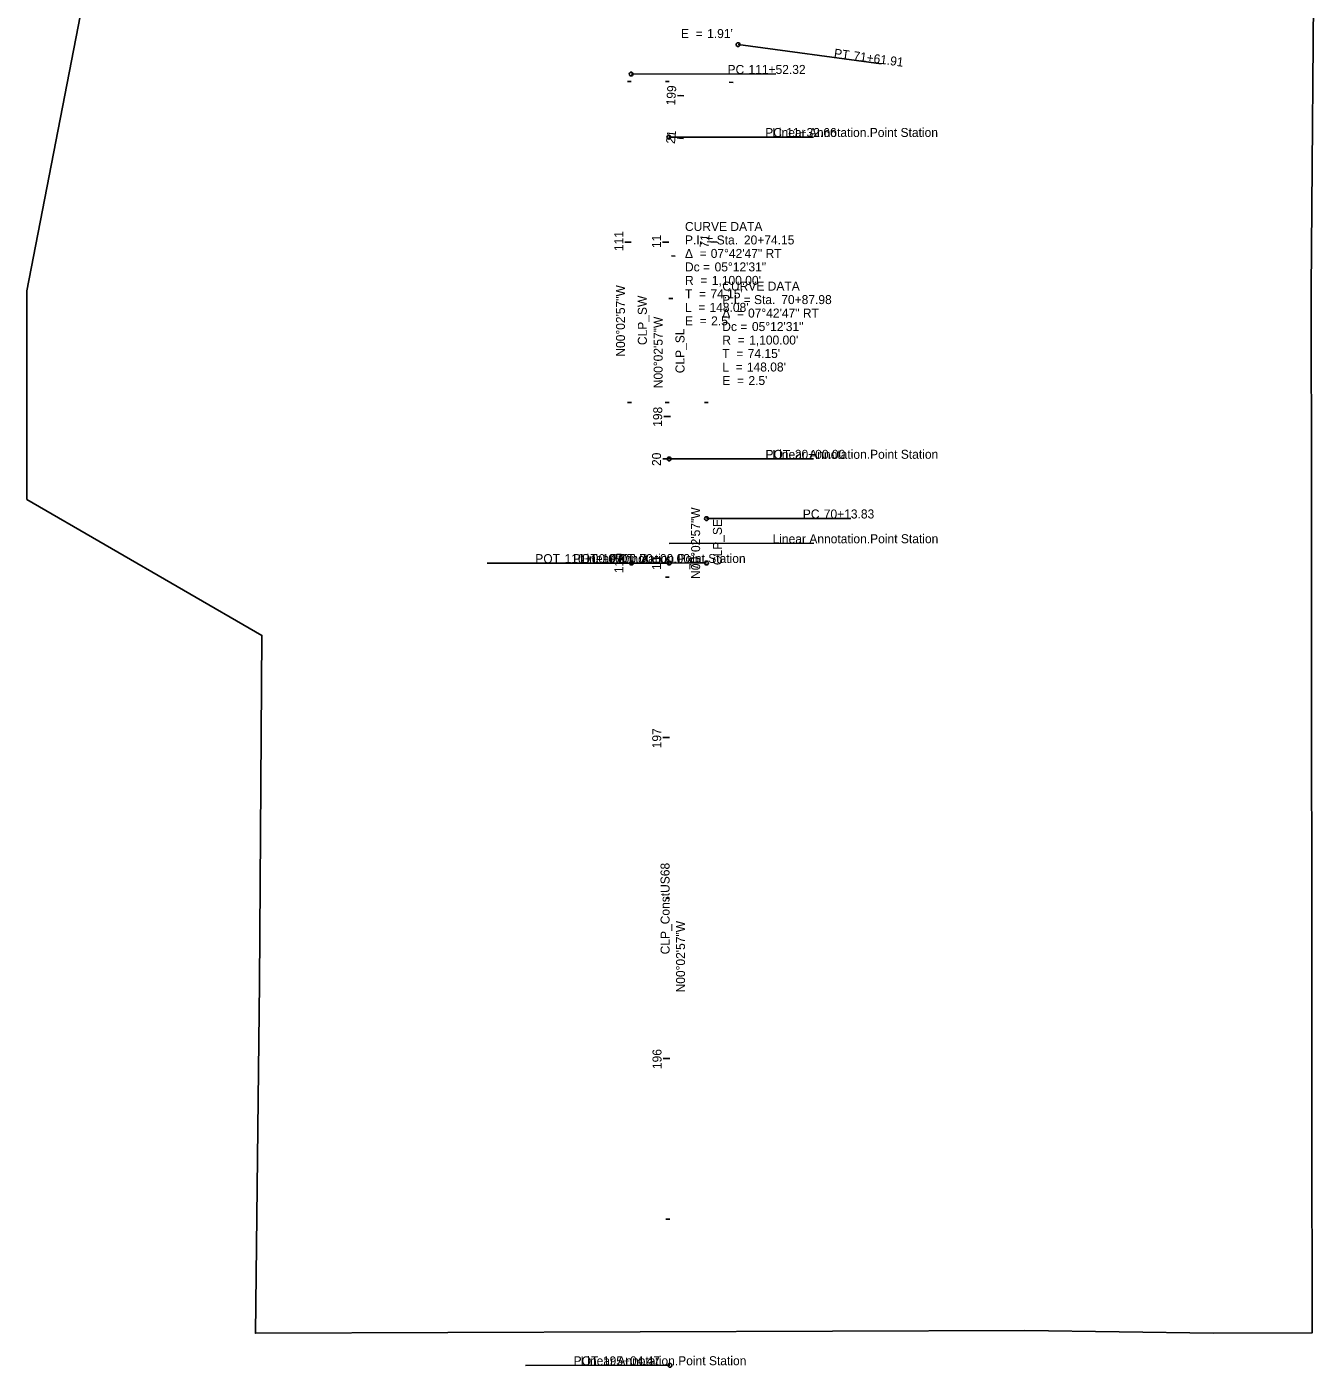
# Model space of a CAD drawing. Extents: x 1564517 to 1565226, y 635740 to 637455.
# Drawn here: x 1564587.2 to 1564988.1, y 635740 to 636157.6 of the extents above; entities that cross this region are included whole.
import ezdxf

# ---------------------------------------------------------------- set-up
doc = ezdxf.new("R2010")
doc.units = 0
for name, color, linetype in [('GE_P_Alignment_1000_Bearings', 7, 'Continuous'), ('GE_P_Alignment_1000_Distances', 7, 'Continuous'), ('GE_P_Alignment_100_Cardinal_Points', 7, 'Continuous'), ('GE_P_Alignment_500_Bearings', 7, 'Continuous'), ('GE_P_Alignment_500_Cardinal_Points', 7, 'Continuous'), ('GE_P_Alignment_500_Distances', 7, 'Continuous'), ('GK_Drainage_Nodes', 7, 'Continuous'), ('SC_Scratch10', 7, 'Continuous'), ('TX_P_1000', 7, 'Continuous'), ('UT_P_Water', 7, 'Continuous'), ('UT_P_Water_Cells', 7, 'Continuous'), ('UT_X_Electric', 7, 'Continuous'), ('UT_X_Sanitary_Pressure_Line', 7, 'Continuous'), ('UT_X_Water_Cells', 7, 'Continuous')]:
    doc.layers.add(name, color=color, linetype=linetype)

msp = doc.modelspace()

# ---------------------------------------------------------------- linework, layer by layer
at = {"layer": 'GE_P_Alignment_100_Cardinal_Points'}
msp.add_circle((1564787.45, 635740.63), 0.6, dxfattribs=at)
at = {"layer": 'GE_P_Alignment_500_Cardinal_Points'}
msp.add_line((1564787.45, 635740.63), (1564742.45, 635740.59), dxfattribs=at)
msp.add_circle((1564787.45, 635740.63), 0.6, dxfattribs=at)
at = {"layer": 'TX_P_1000'}
for p, q in [((1564787.13, 636123.19), (1564832.13, 636123.23)), ((1564787.21, 636022.95), (1564832.21, 636022.99)), ((1564787.24, 635996.63), (1564832.24, 635996.67)), ((1564787.24, 635990.53), (1564742.24, 635990.49)), ((1564787.45, 635740.63), (1564742.45, 635740.59))]:
    msp.add_line(p, q, dxfattribs=at)
at = {"layer": 'UT_P_Water_Cells'}
for p, q in [((1564808.66, 636152.01), (1564853.26, 636146.01)), ((1564775.39, 636142.84), (1564820.39, 636142.88)), ((1564791.8, 636136.06), (1564790.61, 636136.14)), ((1564787.13, 636123.19), (1564832.13, 636123.23)), ((1564791.67, 636122.81), (1564790.47, 636122.92)), ((1564775.43, 636090.52), (1564774.23, 636090.52)), ((1564787.15, 636090.53), (1564785.95, 636090.53)), ((1564802.14, 636090.45), (1564800.94, 636090.55)), ((1564787.58, 636036.16), (1564786.38, 636036.18)), ((1564787.21, 636022.95), (1564785.21, 636022.94)), ((1564787.21, 636022.95), (1564832.21, 636022.99)), ((1564798.84, 636004.37), (1564843.84, 636004.41)), ((1564775.52, 635990.52), (1564730.52, 635990.48)), ((1564787.24, 635990.53), (1564742.24, 635990.49)), ((1564798.85, 635990.54), (1564753.85, 635990.5)), ((1564775.52, 635990.52), (1564773.52, 635990.52)), ((1564787.24, 635990.53), (1564785.24, 635990.53)), ((1564798.85, 635990.54), (1564796.85, 635990.54)), ((1564787.29, 635936.16), (1564786.09, 635936.16)), ((1564787.37, 635836.16), (1564786.17, 635836.16))]:
    msp.add_line(p, q, dxfattribs=at)
for centre in [(1564808.66, 636152.01), (1564775.39, 636142.84), (1564787.13, 636123.19), (1564787.21, 636022.95), (1564798.84, 636004.37), (1564775.52, 635990.52), (1564787.24, 635990.53), (1564798.85, 635990.54)]:
    msp.add_circle(centre, 0.6, dxfattribs=at)
at = {"layer": 'UT_X_Electric'}
msp.add_lwpolyline([(1564658.34, 635750.59), (1564898, 635751.43), (1564898, 635751.43), (1564898, 635751.43), (1564956.75, 635750.68), (1564987.45, 635750.7), (1564987.39, 635815.7), (1564987.33, 635880.7), (1564987.28, 635945.7), (1564987.22, 636010.7), (1564987.17, 636075.7), (1564988.09, 636191.25), (1564617.12, 636229.41), (1564587.17, 636075.36), (1564587.22, 636010.36), (1564660.39, 635967.97), (1564659.6, 635859.64), (1564658.34, 635750.59), (1564658.34, 635750.59)], close=True, dxfattribs=at)
at = {"layer": 'UT_X_Sanitary_Pressure_Line'}
for p, q in [((1564808.66, 636152.01), (1564853.26, 636146.01)), ((1564775.39, 636142.84), (1564820.39, 636142.88)), ((1564787.13, 636123.19), (1564832.13, 636123.23)), ((1564787.21, 636022.95), (1564785.21, 636022.94)), ((1564787.21, 636022.95), (1564832.21, 636022.99)), ((1564798.84, 636004.37), (1564843.84, 636004.41)), ((1564775.52, 635990.52), (1564730.52, 635990.48)), ((1564787.24, 635990.53), (1564742.24, 635990.49)), ((1564798.85, 635990.54), (1564753.85, 635990.5)), ((1564775.52, 635990.52), (1564773.52, 635990.52)), ((1564787.24, 635990.53), (1564785.24, 635990.53)), ((1564798.85, 635990.54), (1564796.85, 635990.54))]:
    msp.add_line(p, q, dxfattribs=at)
for centre in [(1564808.66, 636152.01), (1564775.39, 636142.84), (1564787.13, 636123.19), (1564787.21, 636022.95), (1564798.84, 636004.37), (1564775.52, 635990.52), (1564787.24, 635990.53), (1564798.85, 635990.54)]:
    msp.add_circle(centre, 0.6, dxfattribs=at)
at = {"layer": 'UT_X_Water_Cells'}
for p, q in [((1564775.39, 636140.52), (1564774.19, 636140.52)), ((1564787.25, 636140.53), (1564786.06, 636140.55)), ((1564807.14, 636140.2), (1564805.95, 636140.35)), ((1564791.8, 636136.06), (1564789.81, 636136.19)), ((1564791.67, 636122.81), (1564789.68, 636122.99)), ((1564775.43, 636090.52), (1564773.43, 636090.52)), ((1564787.15, 636090.53), (1564785.15, 636090.53)), ((1564802.14, 636090.45), (1564800.14, 636090.61)), ((1564789.09, 636086.14), (1564787.89, 636086.19)), ((1564788.31, 636072.93), (1564787.11, 636072.98)), ((1564775.47, 636040.52), (1564774.27, 636040.52)), ((1564787.2, 636040.53), (1564786, 636040.53)), ((1564799.4, 636040.53), (1564798.2, 636040.57)), ((1564787.58, 636036.16), (1564785.58, 636036.2)), ((1564787.21, 636022.95), (1564785.21, 636022.94)), ((1564775.52, 635990.52), (1564773.52, 635990.52)), ((1564787.24, 635990.53), (1564785.24, 635990.53)), ((1564798.85, 635990.54), (1564796.85, 635990.54)), ((1564787.24, 635986.16), (1564786.04, 635986.16)), ((1564787.29, 635936.16), (1564785.29, 635936.16)), ((1564787.33, 635886.16), (1564786.13, 635886.16)), ((1564787.37, 635836.16), (1564785.37, 635836.16)), ((1564787.42, 635786.16), (1564786.22, 635786.16))]:
    msp.add_line(p, q, dxfattribs=at)
msp.add_circle((1564787.13, 636123.19), 0.6, dxfattribs=at)

# ---------------------------------------------------------------- texts
at = {"layer": 'GE_P_Alignment_1000_Bearings'}
msp.add_text('N00°02\'57"W', height=2.8, rotation=90.0491, dxfattribs=at).set_placement((1564792.16, 635856.77))
at = {"layer": 'GE_P_Alignment_1000_Distances'}
msp.add_text('CLP_ConstUS68', height=2.8, rotation=90.0491, dxfattribs=at).set_placement((1564787.35, 635868.63))
at = {"layer": 'GE_P_Alignment_500_Bearings'}
msp.add_text('N00°02\'57"W', height=2.8, rotation=90.0491, dxfattribs=at).set_placement((1564792.16, 635856.77))
at = {"layer": 'GE_P_Alignment_500_Cardinal_Points'}
for s, p in [('POT', (1564757.45, 635740.61)), ('195+04.47', (1564766.58, 635740.61))]:
    msp.add_text(s, height=2.8, rotation=0.0491, dxfattribs=at).set_placement(p)
at = {"layer": 'GE_P_Alignment_500_Distances'}
msp.add_text('CLP_ConstUS68', height=2.8, rotation=90.0491, dxfattribs=at).set_placement((1564787.35, 635868.63))
at = {"layer": 'GK_Drainage_Nodes'}
for s, p in [('E  = ', (1564790.87, 636154.06)), ("1.91'", (1564799.03, 636154.06)), ('CURVE DATA', (1564792.13, 636093.97)), ('P.I. = Sta. ', (1564792.13, 636089.77)), ('20+74.15', (1564810.49, 636089.77)), ('Δ  = ', (1564792.13, 636085.57)), ('07°42\'47" RT', (1564800.15, 636085.57)), ('Dc = ', (1564792.13, 636081.37)), ('05°12\'31"', (1564801.36, 636081.37)), ('R  = ', (1564792.13, 636077.17)), ("1,100.00'", (1564800.49, 636077.17)), ('CURVE DATA', (1564803.75, 636075.39)), ('T  = ', (1564792.13, 636072.97)), ("74.15'", (1564800.06, 636072.97)), ('P.I. = Sta. ', (1564803.75, 636071.19)), ('70+87.98', (1564822.12, 636071.19)), ('L  = ', (1564792.13, 636068.77)), ("148.08'", (1564799.77, 636068.77)), ('Δ  = ', (1564803.75, 636066.99)), ('07°42\'47" RT', (1564811.77, 636066.99)), ('E  = ', (1564792.13, 636064.57)), ("2.5'", (1564800.28, 636064.57)), ('Dc = ', (1564803.75, 636062.79)), ('05°12\'31"', (1564812.99, 636062.79)), ('R  = ', (1564803.75, 636058.59)), ("1,100.00'", (1564812.12, 636058.59)), ('T  = ', (1564803.75, 636054.39)), ("74.15'", (1564811.68, 636054.39)), ('L  = ', (1564803.75, 636050.19)), ("148.08'", (1564811.4, 636050.19)), ('E  = ', (1564803.75, 636045.99)), ("2.5'", (1564811.9, 636045.99))]:
    msp.add_text(s, height=2.8, dxfattribs=at).set_placement(p)
for s, p in [('N00°02\'57"W', (1564773.46, 636054.81)), ('CLP_SW', (1564780.26, 636058.41)), ('N00°02\'57"W', (1564785.19, 636044.99)), ('CLP_SL', (1564791.99, 636049.64)), ('N00°02\'57"W', (1564796.86, 635985.59)), ('CLP_SE', (1564803.65, 635989.87))]:
    msp.add_text(s, height=2.8, rotation=90.0491, dxfattribs=at).set_placement(p)
at = {"layer": 'SC_Scratch10'}
for s, p in [('E  = ', (1564790.87, 636154.06)), ("1.91'", (1564799.03, 636154.06)), ('CURVE DATA', (1564792.13, 636093.97)), ('P.I. = Sta. ', (1564792.13, 636089.77)), ('20+74.15', (1564810.49, 636089.77)), ('Δ  = ', (1564792.13, 636085.57)), ('07°42\'47" RT', (1564800.15, 636085.57)), ('Dc = ', (1564792.13, 636081.37)), ('05°12\'31"', (1564801.36, 636081.37)), ('R  = ', (1564792.13, 636077.17)), ("1,100.00'", (1564800.49, 636077.17)), ('CURVE DATA', (1564803.75, 636075.39)), ('T  = ', (1564792.13, 636072.97)), ("74.15'", (1564800.06, 636072.97)), ('P.I. = Sta. ', (1564803.75, 636071.19)), ('70+87.98', (1564822.12, 636071.19)), ('L  = ', (1564792.13, 636068.77)), ("148.08'", (1564799.77, 636068.77)), ('Δ  = ', (1564803.75, 636066.99)), ('07°42\'47" RT', (1564811.77, 636066.99)), ('E  = ', (1564792.13, 636064.57)), ("2.5'", (1564800.28, 636064.57)), ('Dc = ', (1564803.75, 636062.79)), ('05°12\'31"', (1564812.99, 636062.79)), ('R  = ', (1564803.75, 636058.59)), ("1,100.00'", (1564812.12, 636058.59)), ('T  = ', (1564803.75, 636054.39)), ("74.15'", (1564811.68, 636054.39)), ('L  = ', (1564803.75, 636050.19)), ("148.08'", (1564811.4, 636050.19)), ('E  = ', (1564803.75, 636045.99)), ("2.5'", (1564811.9, 636045.99))]:
    msp.add_text(s, height=2.8, dxfattribs=at).set_placement(p)
for s, p in [('N00°02\'57"W', (1564773.46, 636054.81)), ('CLP_SW', (1564780.26, 636058.41)), ('N00°02\'57"W', (1564785.19, 636044.99)), ('CLP_SL', (1564791.99, 636049.64)), ('N00°02\'57"W', (1564796.86, 635985.59)), ('CLP_SE', (1564803.65, 635989.87))]:
    msp.add_text(s, height=2.8, rotation=90.0491, dxfattribs=at).set_placement(p)
at = {"layer": 'TX_P_1000'}
for p in [(1564819.3, 636123.22), (1564819.39, 636022.97), (1564819.41, 635996.66), (1564759.41, 635990.51), (1564759.63, 635740.61)]:
    msp.add_text('Linear Annotation.Point Station', height=2.8, rotation=0.0491, dxfattribs=at).set_placement(p)
at = {"layer": 'UT_P_Water'}
for s, p in [('E  = ', (1564790.87, 636154.06)), ("1.91'", (1564799.03, 636154.06)), ('CURVE DATA', (1564792.13, 636093.97)), ('P.I. = Sta. ', (1564792.13, 636089.77)), ('20+74.15', (1564810.49, 636089.77)), ('Δ  = ', (1564792.13, 636085.57)), ('07°42\'47" RT', (1564800.15, 636085.57)), ('Dc = ', (1564792.13, 636081.37)), ('05°12\'31"', (1564801.36, 636081.37)), ('R  = ', (1564792.13, 636077.17)), ("1,100.00'", (1564800.49, 636077.17)), ('CURVE DATA', (1564803.75, 636075.39)), ('T  = ', (1564792.13, 636072.97)), ("74.15'", (1564800.06, 636072.97)), ('P.I. = Sta. ', (1564803.75, 636071.19)), ('70+87.98', (1564822.12, 636071.19)), ('L  = ', (1564792.13, 636068.77)), ("148.08'", (1564799.77, 636068.77)), ('Δ  = ', (1564803.75, 636066.99)), ('07°42\'47" RT', (1564811.77, 636066.99)), ('E  = ', (1564792.13, 636064.57)), ("2.5'", (1564800.28, 636064.57)), ('Dc = ', (1564803.75, 636062.79)), ('05°12\'31"', (1564812.99, 636062.79)), ('R  = ', (1564803.75, 636058.59)), ("1,100.00'", (1564812.12, 636058.59)), ('T  = ', (1564803.75, 636054.39)), ("74.15'", (1564811.68, 636054.39)), ('L  = ', (1564803.75, 636050.19)), ("148.08'", (1564811.4, 636050.19)), ('E  = ', (1564803.75, 636045.99)), ("2.5'", (1564811.9, 636045.99))]:
    msp.add_text(s, height=2.8, dxfattribs=at).set_placement(p)
for s, p in [('N00°02\'57"W', (1564773.46, 636054.81)), ('CLP_SW', (1564780.26, 636058.41)), ('N00°02\'57"W', (1564785.19, 636044.99)), ('CLP_SL', (1564791.99, 636049.64)), ('N00°02\'57"W', (1564796.86, 635985.59)), ('CLP_SE', (1564803.65, 635989.87))]:
    msp.add_text(s, height=2.8, rotation=90.0491, dxfattribs=at).set_placement(p)
at = {"layer": 'UT_P_Water_Cells'}
for s, rotation, p in [('PT', 352.3361, (1564838.4, 636148.01)), ('71+61.91', 352.3361, (1564844.43, 636147.2)), ('PC', 0.0491, (1564805.39, 636142.87)), ('111+52.32', 0.0491, (1564811.91, 636142.87)), ('PC', 0.0491, (1564817.13, 636123.22)), ('11+32.66', 0.0491, (1564823.65, 636123.22)), ('20', 90.0491, (1564784.67, 636020.75)), ('POT', 0.0491, (1564817.21, 636022.97)), ('20+00.00', 0.0491, (1564826.34, 636022.98)), ('PC', 0.0491, (1564828.84, 636004.4)), ('70+13.83', 0.0491, (1564835.36, 636004.4)), ('POT', 0.0491, (1564745.52, 635990.49)), ('110+00.00', 0.0491, (1564754.65, 635990.5)), ('POT', 0.0491, (1564757.24, 635990.5)), ('10+00.00', 0.0491, (1564766.37, 635990.51)), ('POT', 0.0491, (1564768.85, 635990.51)), ('110', 90.0491, (1564772.97, 635987.38)), ('70+00.00', 0.0491, (1564777.98, 635990.52)), ('10', 90.0491, (1564784.7, 635988.34)), ('70', 90.0491, (1564796.31, 635988.34))]:
    msp.add_text(s, height=2.8, rotation=rotation, dxfattribs=at).set_placement(p)
at = {"layer": 'UT_X_Sanitary_Pressure_Line'}
for s, rotation, p in [('PT', 352.3361, (1564838.4, 636148.01)), ('71+61.91', 352.3361, (1564844.43, 636147.2)), ('PC', 0.0491, (1564805.39, 636142.87)), ('111+52.32', 0.0491, (1564811.91, 636142.87)), ('PC', 0.0491, (1564817.13, 636123.22)), ('11+32.66', 0.0491, (1564823.65, 636123.22)), ('20', 90.0491, (1564784.67, 636020.75)), ('POT', 0.0491, (1564817.21, 636022.97)), ('20+00.00', 0.0491, (1564826.34, 636022.98)), ('PC', 0.0491, (1564828.84, 636004.4)), ('70+13.83', 0.0491, (1564835.36, 636004.4)), ('POT', 0.0491, (1564745.52, 635990.49)), ('110+00.00', 0.0491, (1564754.65, 635990.5)), ('POT', 0.0491, (1564757.24, 635990.5)), ('10+00.00', 0.0491, (1564766.37, 635990.51)), ('POT', 0.0491, (1564768.85, 635990.51)), ('110', 90.0491, (1564772.97, 635987.38)), ('70+00.00', 0.0491, (1564777.98, 635990.52)), ('10', 90.0491, (1564784.7, 635988.34)), ('70', 90.0491, (1564796.31, 635988.34))]:
    msp.add_text(s, height=2.8, rotation=rotation, dxfattribs=at).set_placement(p)
at = {"layer": 'UT_X_Water_Cells'}
for s, rotation, p in [('199', 86.1971, (1564789.05, 636132.99)), ('21', 84.8404, (1564789, 636121.02)), ('111', 90.0491, (1564772.93, 636087.7)), ('11', 90.0491, (1564784.66, 636088.65)), ('71', 85.5609, (1564799.49, 636088.63)), ('198', 88.9578, (1564784.97, 636032.93)), ('20', 90.0491, (1564784.67, 636020.75)), ('110', 90.0491, (1564772.97, 635987.38)), ('10', 90.0491, (1564784.7, 635988.34)), ('70', 90.0491, (1564796.31, 635988.34)), ('197', 90.0491, (1564784.74, 635932.82)), ('196', 90.0491, (1564784.83, 635832.88))]:
    msp.add_text(s, height=2.8, rotation=rotation, dxfattribs=at).set_placement(p)

doc.saveas('drawing.dxf')
